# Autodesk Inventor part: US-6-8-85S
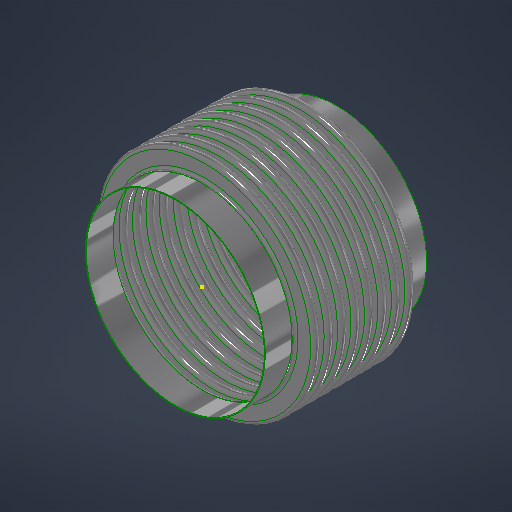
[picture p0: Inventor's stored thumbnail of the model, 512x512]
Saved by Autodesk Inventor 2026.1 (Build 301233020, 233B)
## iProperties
Category: 22 GA (0.030 THICK)
RuleStatus: InUse
Created: 2026-07
Part Number: US-6-8-85S
Project: =STOCK BELLOWS: <Stock Number><SFILL>
Material: ASTM A240-304
Description: =STOCK BELLOWS: <Stock Number>, <SID_> I.D., <SOD_> O.D., <SPLY_> PLY, <Category>, <SNET_CONS> CONS.<PITCH_><STANGENT_> TANGENT<SFILL>
Document SubType Name: Sheet Metal
Designer: LC
Stock Number: U.S-6-8-85S
Surface Area: 659.127 cm^2
Volume: 56.61 cm^3
Sheet Metal Rule: Default
Appearance: STAINLESS STEEL
NET_TUBE: 3.428
COUNTER: 1.500
PBAR: 1.214
PSET: 5.356
PLY: 2
CONS: 2
THK: 0.036
ID: 4.500
OD: 5.500
CONS_: 2
TANGENT: 0.500
PITCH: 0.375
BELLOWS_UPSET: 0.000
NET_CONS: 2
S_CONS: 0
Description_Units: 0
ID_M: 114.30 mm
OD_M: 139.70 mm
THK_M: 0.91 mm
ID_U: 4.500 in
OD_U: 5.500 in
THK_U: 0.036 in
TANGENT2: 0.500
d79: 1.000
d82: 1.000
d83: 26.000
d84: 24.000
d80: 2.571
d81: 10
SID: 2.375
SCONS_: 8
SPITCH: 0.250
SBELLOWS_UPSET: 0.000
SNET_CONS: 8
SS_CONS: 0
SCONS: 8
d174: 8
d177: 0.018
d178: 2.375
d179: 3.000
d180: 0.375
d181: 1.000
d182: 0.000
d190: 8
d191: 1
d192: 1
d193: 8
d194: 0
PART_NUMBER: U.S-6-8-85S
PRESSURE: 85
SIZE: 6.00
STANGENT_: 1.000
d214: 8
d217: 0.030
d218: 6.625
d219: 8.125
d220: 0.500
d221: 1.000
d222: 0.000
d230: 8
d231: 1
d232: 1
d233: 8
d234: 0
STANGENT: 4.000
SPLY_: 1
STHK_: 0.030
SID_: 6.625
SOD_: 8.125
SPITCH_: 0.500
STANGENT__: 1.000
SBELLOWS_UPSET_: 0.000
SDIFF_TAN: 1.000
TAN_TO_TAN: 0.750 in
d252: 2
d275: 2
d287: 0.050
d289: 0.500
d290: 0.000
d263: 2
d265: 1
d268: 2
d269: 0
d286: 2
d288: 1
d291: 2
d292: 0
SOD_NECK: 6 11/16
CFILL: .
SFILL: .
PITCH_: =, <SPITCH_> PITCH,
SREROLL: 0.750
MATTABLE: 20 GA (0.036 THICK)
MESH: ,
CSECT: 2
Author: LC
Keywords: 20 GA (0.036 THICK)
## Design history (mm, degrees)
sketch "Sketch2"
  geometry: L1 (0, -183.595)-(0, 600.956) reference; L2 (58.979, 0)-(57.15, 0); L3 (60.446, -1.467)-(66.554, -1.467); L4 (60.446, -3.296)-(66.554, -3.296); L5 (66.554, -8.058)-(60.446, -8.058); L6 (66.554, -6.229)-(60.446, -6.229); L7 (58.979, -9.525)-(57.15, -9.525); L8 (60.446, 0)-(60.446, -9.525); L9 (66.554, -4.762)-(69.85, -4.763); L10 (57.15, 0)-(57.15, -9.525); L11 (20.376, 102.841)-(20.376, 101.926); L12 (58.262, 488.877)-(58.262, 349.177); L13 (58.262, 479.352)-(58.262, 339.652); L14 (93.133, -58.817)-(93.133, -71.517); L15 (118.746, -66.401)-(118.746, -66.401); L16 (66.554, -6.229)-(66.554, -8.058); L17 (60.446, -6.229)-(60.446, -8.058); L18 (60.446, -7.144)-(66.554, -7.144); L19 (69.85, 0)-(69.85, -9.525); L20 (-66.554, -6.229)-(-66.554, -8.058); L21 (-66.554, -1.467)-(-60.446, -1.467); L22 (-66.554, -3.296)-(-60.446, -3.296); L23 (-60.446, -6.229)-(-66.554, -6.229); L24 (-66.554, -7.144)-(-60.446, -7.144); L25 (-60.446, -8.058)-(-66.554, -8.058); L26 (-60.446, -6.229)-(-60.446, -8.058); L27 (-57.15, -2.522)-(-57.15, -12.047); L28 (-60.446, -4.763)-(-57.15, -4.763); L29 (-66.554, 3.828)-(-66.554, -9.525); L30 (-68.021, 0)-(-69.85, 0); L31 (-69.85, 0)-(-69.85, -9.525); L32 (-68.021, -9.525)-(-69.85, -9.525); A1 r 1.467 centre (60.446, 0) between (58.979, 0) and (60.446, -1.467); A2 r 3.296 centre (60.446, 0) between (57.15, 0) and (60.446, -3.296); A3 r 3.296 centre (66.554, -4.762) between (66.554, -8.058) and (66.554, -1.467); A4 r 1.467 centre (66.554, -4.762) between (66.554, -6.229) and (66.554, -3.296); A5 r 1.467 centre (60.446, -9.525) between (60.446, -8.058) and (58.979, -9.525); A6 r 3.296 centre (60.446, -9.525) between (60.446, -6.229) and (57.15, -9.525); A7 r 2.381 centre (66.554, -4.762) between (66.554, -7.144) and (68.936, -4.762); A8 r 2.381 centre (60.446, -9.525) between (60.446, -7.144) and (58.064, -9.525); A9 r 1.467 centre (-66.554, -9.525) between (-66.554, -8.058) and (-68.021, -9.525); A10 r 1.467 centre (-60.446, -4.763) between (-60.446, -6.229) and (-60.446, -3.296); A11 r 2.381 centre (-60.446, -4.763) between (-60.446, -7.144) and (-58.064, -4.763); A12 r 3.296 centre (-60.446, -4.763) between (-60.446, -8.058) and (-60.446, -1.467); A13 r 2.381 centre (-66.554, -9.525) between (-66.554, -7.144) and (-68.936, -9.525); A14 r 3.296 centre (-66.554, -9.525) between (-66.554, -6.229) and (-69.85, -9.525); A15 r 1.467 centre (-66.554, 0) between (-68.021, 0) and (-66.554, -1.467); A16 r 3.296 centre (-66.554, 0) between (-69.85, 0) and (-66.554, -3.296); 10 further points
  constraints: 62 end point, 38 point on circle, 20 tangent, 16 centre point, 12 parallel, 9 midpoint, 7 vertical, 6 coincident, 6 concentric, 6 point on line, 4 equal radius, 4 perpendicular, 3 horizontal, 1 collinear, 1 horizontal alignment, 10 other
  dimensions: "THK" = 0.9144 distance of L11.start L11.end; "ID" = 114.3 distance of L11.end point (20.376, -12.374); "OD" = 139.7 distance of L12.start L12.end; "PITCH" = 9.525 distance of L12.start L13.start; "TANGENT" = 12.7 distance of L14.start L14.end; "BELLOWS_UPSET" = 0 distance of L15.start L15.end; "d43" = 114.3 diameter of L10 L1 (= ID); "d44" = 139.7 diameter of L9.end L1 (= OD); "d45" = 1.8288 distance between parallel lines of L5 L6 (computed from THK, PLY); "d46" = 3.29565 radius of A3 (computed from PITCH, THK, PLY); "UPSET_PITCH" = 9.525 distance of L2.end L7.end (derived); "SIDEWALL_ANGLE" = 0 deg angle of L3 L9 (derived); "CON_GAP" = 2.9337 distance of point (60.446, -6.229) point (60.446, -3.296) (derived); "TAN1" = 3.74046 dimension on A8 (derived); "TAN2" = 3.74046 dimension on A7 (derived); "LEG1" = 6.1087 distance of L18.start L18.end (derived); "d278" = 1.8288 distance between parallel lines of L25 L23 (derived); "d279" = 3.29565 radius of A12 (derived); "d280" = 9.525 distance of L30.end L31.end (derived); "d281" = 360 deg dimension on L21 L28 (derived); "d282" = 2.9337 distance of point (-66.554, -6.229) point (-66.554, -3.296) (derived); "d283" = 3.74046 dimension on A13 (derived); "d284" = 3.74046 dimension on A11 (derived); "d285" = 6.1087 distance of L24.start L24.end (derived); "d293" = 114.3 diameter of L27 L1 (derived); "d294" = 139.7 diameter of L31 L1 (derived)
  node "Sketch Rectangular Pattern1" dims "d31" = 25.4, "ID" = 114.3
  node "Sketch Rectangular Pattern2" dims "d39" = 25.4, "PITCH" = 9.525
revolve "CONS" stored, may be unused: angle "d48" = 90 deg
node "BELLOW MIDPLANE"
pattern_linear "Rectangular Pattern2" dims "d52" = 9.525 (= UPSET_PITCH)
sketch "Sketch5"
  geometry: C1 r 58.979 at (0, 0) reference; C2 r 57.15 at (0, 0) reference
extrude "TANGENT" new body sketch "Sketch5" distance "d53" = 12.7 (= TANGENT); taper "d54" = 0 deg
revolve "SAMETAN" stored, may be unused: angle "d65" = 90 deg
revolve "DIFFTAN" stored, may be unused: angle "d70" = 90 deg
sketch "Sketch9"
  geometry: L1 (58.391, 0)-(-58.391, 0) reference; L2 (0, -17.78)-(0, 17.78) reference; L3 (41.708, 0)-(-41.708, 0); L4 (41.708, -11.906)-(41.708, 11.906); L5 (29.008, -11.906)-(29.008, 11.906); L6 (15.418, 11.906)-(15.418, -11.906); L7 (-29.008, -11.906)-(-29.008, 11.906); L8 (-41.708, -11.906)-(-41.708, 11.906); L9 (40.914, -11.906)-(40.914, 11.906); L10 (41.708, -11.906)-(40.914, -11.906); L11 (41.708, 11.906)-(40.914, 11.906); L12 (15.815, 11.906)-(15.022, 11.906); L13 (15.022, 11.906)-(15.022, -11.906); L14 (15.022, -11.906)-(15.815, -11.906); L15 (15.815, -11.906)-(15.815, 11.906); L16 (-15.815, 11.906)-(-15.815, -11.906); L17 (-15.418, 11.906)-(-15.418, -11.906); L18 (-15.815, -11.906)-(-15.022, -11.906); L19 (-15.022, -11.906)-(-15.022, 11.906); L20 (-15.022, 11.906)-(-15.815, 11.906); L21 (-41.708, -11.906)-(-40.914, -11.906); L22 (-40.914, -11.906)-(-40.914, 11.906); L23 (-40.914, 11.906)-(-41.708, 11.906); L24 (-41.708, 11.906)-(-41.708, -11.906); L25 (41.708, -0.397)-(-41.708, -0.397); L26 (-41.708, -0.397)-(-41.708, 0.397); L27 (-41.708, 0.397)-(41.708, 0.397); L28 (41.708, 0.397)-(41.708, -0.397); L29 (-41.708, 11.906)-(41.708, 11.906); L30 (41.708, 11.906)-(41.708, 12.7); L31 (41.708, 12.7)-(-41.708, 12.7); L32 (-41.708, 12.7)-(-41.708, 11.906); L33 (41.708, -11.906)-(-41.708, -11.906); L34 (-41.708, -11.906)-(-41.708, -12.7); L35 (-41.708, -12.7)-(41.708, -12.7); L36 (41.708, -12.7)-(41.708, -11.906); 30 further points
  constraints: 68 end point, 13 midpoint, 13 parallel, 8 horizontal, 7 perpendicular, 6 equal length, 3 point on line, 2 vertical, 14 other
  dimensions: "d115" = 23.8125 distance of L4.start L4.end (derived); "d116" = 12.7 distance between parallel lines of L4 L5 (derived); "d117" = 13.58962 distance between parallel lines of L5 L6 (derived); "d125" = 44.42645 distance between parallel lines of L7 L6 (derived); "d127" = 12.7 distance between parallel lines of L8 L7 (derived); "d128" = 26.28962 distance between parallel lines of L6 L4 (derived); "d130" = 83.41607 distance between parallel lines of L8 L4 (derived); "RULER_THK" = 0.79375 distance between parallel lines of L4 L9; "d135" = 0.79375 distance of L13.end L14.end (derived); "d138" = 30.83684 distance of L13.end L16.end (derived); "d143" = 0.79375 distance of L22.end L8.end (derived); "d144" = 0.79375 distance between parallel lines of L27 L25 (derived)
extrude "RULER" join sketch "Sketch9" distance "d149" = 0.79375 (derived); taper "d150" = 0 deg
extrude "BARS" join sketch "Sketch9" distance "d151" = 0.79375 (derived); taper "d152" = 0 deg
pattern_linear "Rectangular Pattern4" dims "d155" = 30.83684 (derived)
sketch "Sketch13"
  geometry: L1 (93.149, -52.467)-(93.149, -77.867); L2 (84.9, 0)-(84.138, 0); L3 (84.9, -12.7)-(84.138, -12.7); L4 (99.631, -9.906)-(87.694, -9.906); L5 (99.631, -9.144)-(87.694, -9.144); L6 (99.631, -6.35)-(103.188, -6.35); L7 (87.694, -2.794)-(99.631, -2.794); L8 (87.694, 0)-(87.694, -12.7); L9 (84.138, 0)-(84.138, -12.7); L10 (58.254, -329.214)-(58.254, -535.589); L11 (58.254, -341.914)-(58.254, -548.289); L12 (58.254, -367.314)-(58.254, -573.689); L13 (58.254, -380.014)-(58.254, -586.389); L14 (58.254, -392.714)-(58.254, -599.089); L15 (58.254, -405.414)-(58.254, -611.789); L16 (58.254, -418.114)-(58.254, -624.489); L17 (58.254, -354.614)-(58.254, -560.989); L18 (20.376, 102.688)-(20.376, 101.926); L19 (87.694, -3.556)-(99.631, -3.556); L20 (0, -717.834)-(0, 239.264) reference; L21 (-23.752, 0)-(142.514, 0) reference; A1 r 2.794 centre (87.694, 0) between (84.9, 0) and (87.694, -2.794); A2 r 2.794 centre (87.694, -12.7) between (87.694, -9.906) and (84.9, -12.7); A3 r 3.556 centre (87.694, -12.7) between (87.694, -9.144) and (84.138, -12.7); A4 r 2.794 centre (99.631, -6.35) between (99.631, -9.144) and (99.631, -3.556); A5 r 3.556 centre (99.631, -6.35) between (99.631, -9.906) and (99.631, -2.794); A6 r 3.556 centre (87.694, 0) between (84.138, 0) and (87.694, -3.556); 6 further points; 1 other entity
  constraints: 38 end point, 15 point on circle, 9 tangent, 6 centre point, 6 parallel, 5 vertical alignment, 4 point on line, 4 vertical, 3 coincident, 3 concentric, 2 collinear, 2 equal radius, 1 horizontal, 1 perpendicular, 23 other
  dimensions: "SBELLOWS_UPSET_" = 0 distance of point (118.762, -66.401) point (118.762, -66.401); "STOTAL_THK_BELLOW__" = 0.762 distance between parallel lines of L4 L5 (derived); "d224" = 3.556 radius of A5 (derived); "d225" = 12.7 distance of L2.end L3.end (derived); "SSIDEWALL_ANGLE_" = 0 deg angle of L7 L6 (derived); "SSCON_GAP_" = 5.588 distance of point (87.694, -9.144) point (87.694, -3.556) (derived); "d235" = 168.275 diameter of L9 L20 (derived); "d236" = 206.375 diameter of L6.end L20 (derived)
  node "Sketch Rectangular Pattern4" dims "d228" = 25.4
  node "Sketch Rectangular Pattern5" dims "d229" = 25.4
revolve "SBELLOW" stored, may be unused: angle "d197" = 90 deg
pattern_linear "Rectangular Pattern5" dims "d204" = 12.7 (derived)
revolve "STANGENT" stored, may be unused: angle "d240" = 90 deg
revolve "SSAMETAN" stored, may be unused: angle "d241" = 90 deg
revolve "SDIFFTAN" stored, may be unused: angle "d246" = 90 deg
revolve "INVCON" stored, may be unused: angle "d295" = 90 deg
pattern_linear "Rectangular Pattern6" dims "d298" = 9.525 (derived)
revolve "INVTANGENT" stored, may be unused: angle "d302" = 90 deg
revolve "INVSAMETAN" stored, may be unused: angle "d307" = 90 deg
revolve "INVDIFFTAN" stored, may be unused: angle "d312" = 90 deg
sketch "ID BELLOW MOUNT CALC"
  geometry: L1 (44.45, 0)-(38.1, 0); L2 (38.1, 0)-(38.1, 12.7); L3 (38.1, 12.7)-(44.45, 12.7); L4 (44.45, 12.7)-(44.45, 0); L5 (36.513, 12.7)-(34.684, 12.7); L6 (34.684, 12.7)-(34.684, 0); L7 (34.684, 0)-(36.513, 0); L8 (36.513, 0)-(36.513, 12.7); L9 (0, -2.54)-(0, 15.24) reference; L10 (-8.89, 0)-(53.34, 0) reference; 1 further point
  constraints: 16 end point, 5 parallel, 2 collinear, 2 horizontal, 2 perpendicular
  dimensions: "d314" = 12.7 distance of L5.end L6.end (derived); "d315" = 1.8288 distance of L5.start L5.end (derived); "IG" = 1.5875 distance between parallel lines of L2 L8; "PIPE_OD" = 88.9 diameter of L4 L9; "PIPE_WALL" = 6.35 distance of L2.end L3.end; "ID_MT_BELLOW" = 69.3674 diameter of L6 L9 (derived)
revolve "CFILL" stored, may be unused: angle "d320" = 90 deg
pattern_linear "Rectangular Pattern7" dims "d323" = 9.525 (derived)
revolve "SFILL" stored, may be unused: angle "d324" = 90 deg
pattern_linear "Rectangular Pattern8" dims "d327" = 12.7 (derived)
node "STOCK BELLOW MIDPLANE"
sketch "Sketch21"
  geometry: L1 (0, -144.462)-(0, 144.462) reference; L2 (-144.462, 0)-(144.462, 0) reference; L3 (-0.099, 71.437)-(0.099, 71.437); L4 (0.099, 71.437)-(0.099, 55.562); L5 (0.099, 55.562)-(-0.099, 55.562); L6 (-0.099, 55.562)-(-0.099, 71.437); C1 r 55.562 at (0, 0); C2 r 71.437 at (0, 0); 3 further points
  constraints: 8 end point, 2 centre point, 2 coincident, 2 parallel, 2 tangent, 1 horizontal, 1 perpendicular, 1 other
  dimensions: "d329" = 111.125 diameter of C1 (derived); "d330" = 142.875 diameter of C2 (derived); "d331" = 0.19844 distance of L3.start L3.end
extrude "CLAMSHELL" cut sketch "Sketch21" extent not by distance; stored distance "d332" = 0; taper "d333" = 0 deg
pattern_circular "Circular Pattern1" dims angle "d335" = 180 deg (derived)
node "BELLOW"
sketch "Sketch6"
  geometry: L1 (-19.05, 58.979)-(-6.35, 58.979); L2 (-6.35, 58.979)-(-6.35, 57.15); L3 (-6.35, 57.15)-(-19.05, 57.15); L4 (-19.05, 57.15)-(-19.05, 58.979); L5 (2.54, 0)-(-59.69, 0) reference; L6 (-38.1, -108.388)-(-38.1, 156.601) reference; 1 further point
  constraints: 8 end point, 2 parallel, 1 horizontal, 1 perpendicular
  dimensions: "d61" = 12.7 distance of L2.end L3.end (derived); "d62" = 1.8288 distance of L1.end L2.end (derived); "d63" = 114.3 diameter of L3 L5 (derived); "d64" = 19.05 distance between parallel lines of L4 L6 (derived)
sketch "Sketch12"
  geometry: 1 further point
sketch "Sketch14"
  geometry: L1 (-25.4, 84.9)-(0, 84.9); L2 (0, 84.9)-(0, 84.138); L3 (0, 84.138)-(-25.4, 84.138); L4 (-25.4, 84.138)-(-25.4, 84.9); L5 (5.08, 0)-(-30.48, 0) reference; L6 (0, -14.252)-(0, 85.512) reference; 1 further point
  constraints: 8 end point, 2 parallel, 1 collinear, 1 horizontal, 1 perpendicular
  dimensions: "d237" = 0.762 distance of L3.end L1.start (derived); "d238" = 168.275 diameter of L3 L5 (derived); "d239" = 25.4 distance of L1.start L1.end (derived); "SOD_NECK" = 169.799 diameter of L1 L5 (derived)
sketch "Sketch15"
  geometry: L1 (-14.252, 0)-(85.512, 0) reference; L2 (84.138, -101.6)-(84.9, -101.6); L3 (84.9, -101.6)-(84.9, -127); L4 (84.9, -127)-(84.138, -127); L5 (84.138, -127)-(84.138, -101.6); L6 (0, -124.46)-(0, 35.56) reference; 1 further point
  constraints: 8 end point, 2 parallel, 1 horizontal, 1 perpendicular
  dimensions: "d205" = 25.4 distance of L4.end L2.start (derived); "d206" = 0.762 distance of L3.end L4.end (derived); "d207" = 168.275 diameter of L5 L6 (derived); "d208" = 101.6 distance between parallel lines of L1 L2 (derived)
node "TANGENT_"
node "SAME_TAN"
sketch "Sketch8"
  geometry: L1 (58.979, -19.05)-(57.15, -19.05); L2 (57.15, -19.05)-(57.15, -31.75); L3 (57.15, -31.75)-(58.979, -31.75); L4 (58.979, -31.75)-(58.979, -19.05); L5 (0, -40.64)-(0, 21.59) reference; L6 (-108.388, 0)-(156.601, 0) reference; 1 further point
  constraints: 8 end point, 2 parallel, 1 horizontal, 1 perpendicular
  dimensions: "d66" = 114.3 diameter of L2 L5 (derived); "TOTAL_THK_BELLOW" = 1.8288 distance of L2.end L3.end (derived); "d68" = 19.05 distance between parallel lines of L1 L6 (derived); "d69" = 12.7 distance of L1.end L2.end (derived)
node "DIFF_TAN"
node "Sketch Rectangular Pattern3" dims "d138" = 30.83684 (derived), "d141" = 25.4
node "SBELLOW_"
node "STANGENT_"
node "SSAME_TAN"
sketch "Sketch16"
  geometry: L1 (84.9, -101.6)-(84.138, -101.6); L2 (84.138, -101.6)-(84.138, -127); L3 (84.138, -127)-(84.9, -127); L4 (84.9, -127)-(84.9, -101.6); L5 (0, -124.46)-(0, 35.56) reference; L6 (-14.252, 0)-(85.512, 0) reference; 1 further point
  constraints: 8 end point, 2 parallel, 1 horizontal, 1 perpendicular
  dimensions: "SDIFF_TAN" = 25.4 distance of L3.end L1.start; "d243" = 0.762 distance of L2.end L3.end (derived); "d244" = 101.6 distance between parallel lines of L1 L6 (derived); "d245" = 168.275 diameter of L2 L5 (derived)
node "SDIFF_TAN"
body "Solid15"
sketch "Sketch17"
  geometry: L1 (69.85, 12.7)-(68.021, 12.7); L2 (68.021, 12.7)-(68.021, 0); L3 (68.021, 0)-(69.85, 0); L4 (69.85, 0)-(69.85, 12.7); L5 (0, -2.54)-(0, 15.24) reference; L6 (-13.97, 0)-(83.82, 0) reference; 2 further points
  constraints: 8 end point, 2 parallel, 1 horizontal, 1 midpoint, 1 perpendicular, 1 point on line
  dimensions: "INVTANGENT" = 12.7 distance of L3.end L1.start (derived); "d300" = 1.8288 distance of L1.start L1.end (derived); "d301" = 139.7 diameter of L4 L5 (derived)
body "Solid16"
sketch "Sketch18"
  geometry: L1 (69.85, -19.05)-(68.021, -19.05); L2 (68.021, -19.05)-(68.021, -31.75); L3 (68.021, -31.75)-(69.85, -31.75); L4 (69.85, -31.75)-(69.85, -19.05); L5 (-13.97, 0)-(83.82, 0) reference; L6 (0, -40.64)-(0, 21.59) reference; 1 further point
  constraints: 8 end point, 2 parallel, 1 horizontal, 1 perpendicular
  dimensions: "d303" = 19.05 distance between parallel lines of L1 L5 (derived); "d304" = 12.7 distance of L3.end L1.start (derived); "d305" = 1.8288 distance of L2.end L3.end (derived); "d306" = 139.7 diameter of L4 L6 (derived)
body "Solid17"
sketch "Sketch19"
  geometry: L1 (69.85, -19.05)-(68.021, -19.05); L2 (68.021, -19.05)-(68.021, -31.75); L3 (68.021, -31.75)-(69.85, -31.75); L4 (69.85, -31.75)-(69.85, -19.05); L5 (0, -40.64)-(0, 21.59) reference; L6 (-13.97, 0)-(83.82, 0) reference; 1 further point
  constraints: 8 end point, 2 parallel, 1 horizontal, 1 perpendicular
  dimensions: "d308" = 12.7 distance of L1.end L2.end (derived); "d309" = 139.7 diameter of L4 L5 (derived); "d310" = 1.8288 distance of L2.end L3.end (derived); "d311" = 19.05 distance between parallel lines of L1 L6 (derived)
body "Solid18"
body "Solid19"
body "Solid20"
other parameters: "BMPL" = -50.8, "PSET" = 136.0424 (computed from OD, THK, PLY) [user parameter], "PBAR" = 30.83684 (= 0.570796 x PITCH + OD - ID) [user parameter; used in 1 equation term], "COUNTER" = 15 [user parameter], "NET_TUBE" = 87.07367 (computed from CONS_, PBAR, TANGENT) [user parameter], "S_CONS" = 0 [user parameter; used in 1 equation term], "ID_M" = 114.3 (= ID) [user parameter], "OD_M" = 139.7 (= OD) [user parameter], "THK_M" = 0.9144 (= THK) [user parameter], "ID_U" = 114.3 (= ID) [user parameter], "OD_U" = 139.7 (= OD) [user parameter], "THK_U" = 0.9144 (= THK) [user parameter], "D_UNITS" = 0 [user parameter], "TANGENT2" = 12.7 [user parameter], "TAN_TO_TAN" = 19.05 [user parameter], "OD_NECK" = 117.9576 [user parameter], "d79" = 25.4, "d80" = 65.29823 [user parameter], "d82" = 25.4, "d83" = 660.4, "d84" = 609.6, "sa_0" = 4, "FRAME_THK" = 0.79375 [user parameter], "CON_FLAT" = 13.58962 [user parameter], "SID" = 60.325 [user parameter], "SPITCH" = 6.35 [user parameter], "STANGENT_" = 25.4 [user parameter], "SBELLOWS_UPSET" = 0 [user parameter], "SS_CONS" = 0 [user parameter], "STAN_TO_TAN_" = 101.6 [user parameter], "d100" = 0.762 [user parameter], "d191" = 25.4 [user parameter], "d194" = 0 [user parameter], "STANGENT" = 101.6 [user parameter], "d234" = 0 [user parameter], "SUPSET_PITCH_" = 12.7 [user parameter], "d269" = 0 [user parameter], "d287" = 1.27, "d289" = 12.7, "d290" = 0, "d292" = 0 [user parameter], "Thickness" = 3.048 (derived), "KFactor" = 4.4, "BendRadius" = 3.048 (derived), "BendReliefWidth" = 3.048 (derived), "BendReliefDepth" = 1.524 (derived), "CornerReliefSize" = 12.192 (derived), "SeamGap" = 0.00508, "MinimumRemnant" = 6.096 (derived), "TransitionRadius" = 3.048 (derived), "JacobiRadiusSize" = 3.048 (derived), "GapSize" = 3.048 (derived), "SREROLL" = 19.05 [user parameter], "CUR_STK_PITCH" = 12.7 [user parameter], "d328" = -50.8 (derived), "CSECTDEG" = 180 deg [user parameter]
